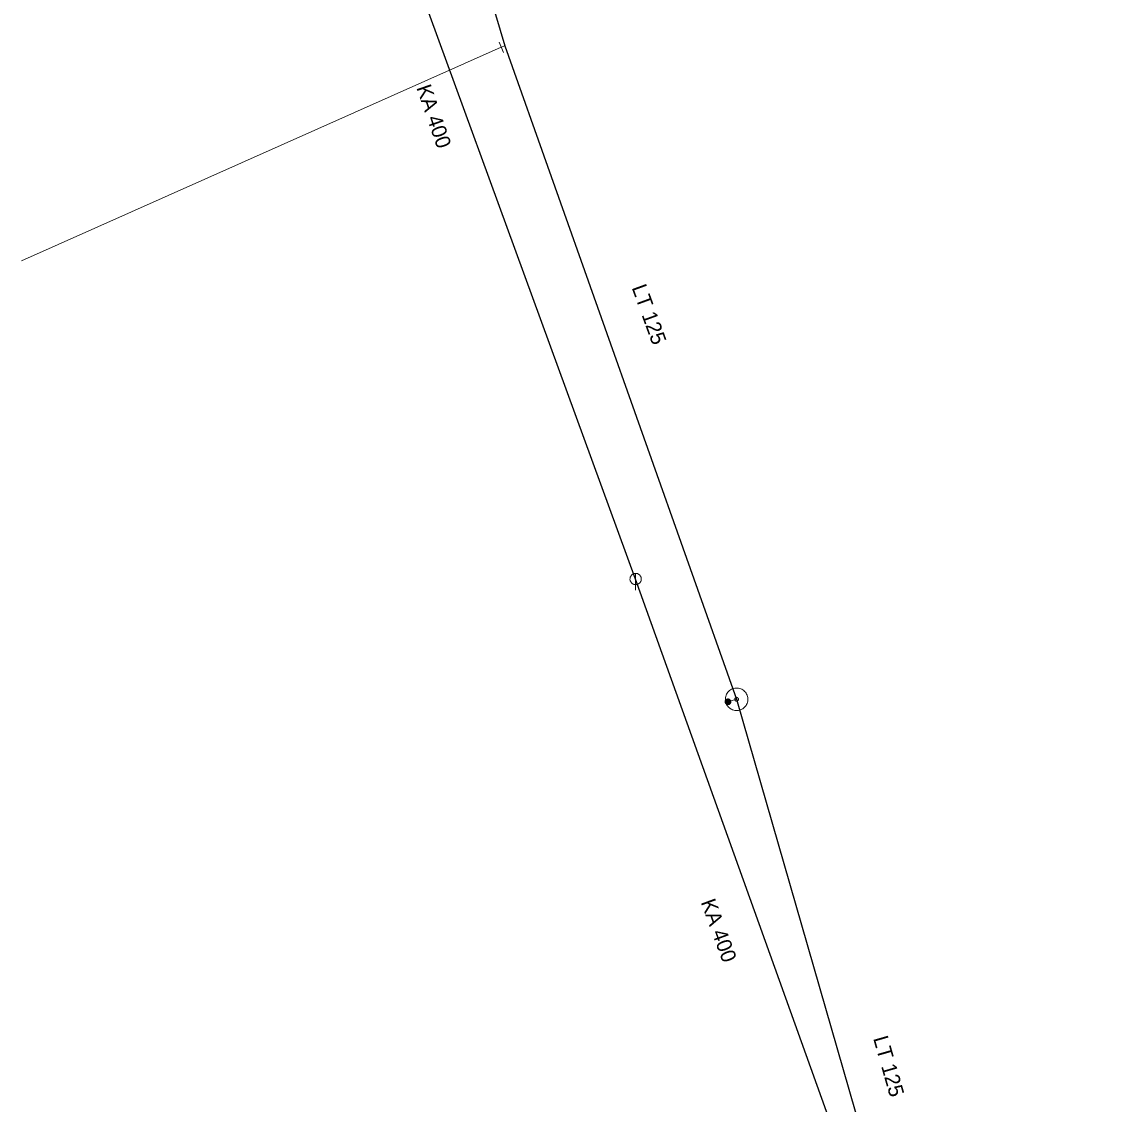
# Model space of a CAD drawing. Extents: x -687515 to -686506, y -974029 to -973461.
# Drawn here: x -687150.06 to -687101.95, y -973553.01 to -973504.79 of the extents above; entities that cross this region are included whole.
import ezdxf
from ezdxf.enums import TextEntityAlignment as Align

# ---------------------------------------------------------------- set-up
doc = ezdxf.new("R2010")
doc.units = 0
doc.header["$LTSCALE"] = 0.27
for name, color, linetype, lineweight in [('1', 7, 'Continuous', 13), ('13', 7, 'Continuous', 13), ('14', 7, 'Continuous', 25), ('17', 7, 'Continuous', 25), ('22', 7, 'Continuous', 13), ('34', 7, 'Continuous', 13), ('47', 7, 'Continuous', 13), ('9', 7, 'Continuous', 13)]:
    doc.layers.add(name, color=color, linetype=linetype, lineweight=lineweight)

msp = doc.modelspace()

# ---------------------------------------------------------------- linework, layer by layer
at = {"layer": '13'}
msp.add_line((-687128.69, -973505.93), (-687150.063, -973515.436), dxfattribs=at)
at = {"layer": '14', "lineweight": 13}
for p, q in [((-687128.537, -973505.866), (-687128.69, -973505.93)), ((-687118.59, -973535.079), (-687118.206, -973534.968))]:
    msp.add_line(p, q, dxfattribs=at)
at = {"layer": '14'}
msp.add_lwpolyline([(-687110.498, -973563.624), (-687122.706, -973529.611), (-687136.829, -973490.92)], dxfattribs=at)
at = {"layer": '17'}
for points in [[(-687132.15, -973493.689), (-687128.537, -973505.866), (-687118.206, -973534.968)], [(-687118.206, -973534.968), (-687107.388, -973572.532), (-687101.954, -973579.133)]]:
    msp.add_lwpolyline(points, dxfattribs=at)
at = {"layer": '22'}
msp.add_line((-687122.705, -973529.359), (-687122.706, -973530.103), dxfattribs=at)
msp.add_lwpolyline([(-687122.454, -973529.611), (-687122.455, -973529.585), (-687122.459, -973529.559), (-687122.465, -973529.533), (-687122.475, -973529.509), (-687122.487, -973529.485), (-687122.501, -973529.463), (-687122.518, -973529.442), (-687122.536, -973529.424), (-687122.557, -973529.407), (-687122.579, -973529.393), (-687122.603, -973529.381), (-687122.627, -973529.371), (-687122.653, -973529.365), (-687122.679, -973529.361), (-687122.705, -973529.359), (-687122.731, -973529.36), (-687122.757, -973529.364), (-687122.783, -973529.37), (-687122.808, -973529.38), (-687122.831, -973529.392), (-687122.853, -973529.406), (-687122.874, -973529.423), (-687122.892, -973529.441), (-687122.909, -973529.462), (-687122.923, -973529.484), (-687122.935, -973529.508), (-687122.945, -973529.532), (-687122.952, -973529.558), (-687122.956, -973529.584), (-687122.958, -973529.61), (-687122.957, -973529.636), (-687122.953, -973529.662), (-687122.946, -973529.688), (-687122.936, -973529.713), (-687122.924, -973529.736), (-687122.91, -973529.758), (-687122.893, -973529.779), (-687122.875, -973529.797), (-687122.854, -973529.814), (-687122.832, -973529.828), (-687122.809, -973529.84), (-687122.784, -973529.85), (-687122.758, -973529.857), (-687122.732, -973529.861), (-687122.706, -973529.863), (-687122.68, -973529.862), (-687122.654, -973529.858), (-687122.628, -973529.851), (-687122.604, -973529.841), (-687122.58, -973529.829), (-687122.558, -973529.815), (-687122.537, -973529.798), (-687122.519, -973529.78), (-687122.502, -973529.759), (-687122.488, -973529.737), (-687122.476, -973529.714), (-687122.466, -973529.689), (-687122.46, -973529.663), (-687122.456, -973529.637)], close=True, dxfattribs=at)
at = {"layer": '34'}
msp.add_line((-687128.79, -973505.703), (-687128.589, -973506.156), dxfattribs=at)
at = {"layer": '47'}
for points in [[(-687118.028, -973535.435), (-687117.98, -973535.414), (-687117.935, -973535.388), (-687117.893, -973535.357), (-687117.854, -973535.323), (-687117.818, -973535.284), (-687117.787, -973535.241), (-687117.762, -973535.196), (-687117.74, -973535.148), (-687117.723, -973535.099), (-687117.712, -973535.048), (-687117.706, -973534.995), (-687117.707, -973534.943), (-687117.711, -973534.891), (-687117.722, -973534.84), (-687117.738, -973534.79), (-687117.759, -973534.742), (-687117.785, -973534.697), (-687117.816, -973534.654), (-687117.85, -973534.616), (-687117.889, -973534.58), (-687117.932, -973534.549), (-687117.978, -973534.523), (-687118.025, -973534.501), (-687118.074, -973534.485), (-687118.125, -973534.474), (-687118.178, -973534.468), (-687118.23, -973534.468), (-687118.282, -973534.473), (-687118.333, -973534.484), (-687118.383, -973534.5), (-687118.431, -973534.521), (-687118.476, -973534.547), (-687118.519, -973534.577), (-687118.557, -973534.612), (-687118.593, -973534.651), (-687118.624, -973534.693), (-687118.651, -973534.739), (-687118.672, -973534.786), (-687118.688, -973534.836), (-687118.699, -973534.887), (-687118.705, -973534.94), (-687118.706, -973534.992), (-687118.7, -973535.044), (-687118.689, -973535.095), (-687118.673, -973535.145), (-687118.652, -973535.193), (-687118.626, -973535.238), (-687118.596, -973535.28), (-687118.561, -973535.319), (-687118.522, -973535.355), (-687118.48, -973535.386), (-687118.435, -973535.412), (-687118.387, -973535.433), (-687118.337, -973535.45), (-687118.286, -973535.461), (-687118.233, -973535.467), (-687118.182, -973535.467), (-687118.129, -973535.462), (-687118.078, -973535.451)], [(-687118.176, -973535.044), (-687118.168, -973535.041), (-687118.161, -973535.036), (-687118.154, -973535.032), (-687118.148, -973535.026), (-687118.142, -973535.019), (-687118.137, -973535.012), (-687118.132, -973535.005), (-687118.129, -973534.997), (-687118.127, -973534.989), (-687118.125, -973534.981), (-687118.124, -973534.972), (-687118.124, -973534.963), (-687118.125, -973534.955), (-687118.126, -973534.947), (-687118.129, -973534.938), (-687118.132, -973534.93), (-687118.137, -973534.923), (-687118.141, -973534.916), (-687118.147, -973534.91), (-687118.154, -973534.904), (-687118.161, -973534.899), (-687118.168, -973534.894), (-687118.176, -973534.891), (-687118.184, -973534.888), (-687118.192, -973534.887), (-687118.201, -973534.886), (-687118.21, -973534.886), (-687118.218, -973534.887), (-687118.226, -973534.888), (-687118.235, -973534.891), (-687118.243, -973534.894), (-687118.25, -973534.899), (-687118.257, -973534.903), (-687118.263, -973534.909), (-687118.269, -973534.916), (-687118.274, -973534.922), (-687118.279, -973534.93), (-687118.282, -973534.938), (-687118.285, -973534.946), (-687118.286, -973534.954), (-687118.287, -973534.963), (-687118.287, -973534.972), (-687118.286, -973534.98), (-687118.285, -973534.988), (-687118.282, -973534.997), (-687118.279, -973535.005), (-687118.274, -973535.012), (-687118.27, -973535.019), (-687118.264, -973535.025), (-687118.257, -973535.031), (-687118.251, -973535.036), (-687118.243, -973535.041), (-687118.235, -973535.044), (-687118.227, -973535.046), (-687118.219, -973535.048), (-687118.21, -973535.049), (-687118.201, -973535.049), (-687118.193, -973535.048), (-687118.185, -973535.047)]]:
    msp.add_lwpolyline(points, close=True, dxfattribs=at)
at = {"layer": '9'}
for points in [[(-687118.463, -973535.079), (-687118.465, -973535.066), (-687118.467, -973535.053), (-687118.47, -973535.04), (-687118.475, -973535.028), (-687118.48, -973535.016), (-687118.488, -973535.005), (-687118.495, -973534.995), (-687118.505, -973534.985), (-687118.516, -973534.977), (-687118.527, -973534.97), (-687118.539, -973534.964), (-687118.551, -973534.959), (-687118.564, -973534.956), (-687118.576, -973534.954), (-687118.59, -973534.953), (-687118.603, -973534.954), (-687118.615, -973534.956), (-687118.629, -973534.959), (-687118.641, -973534.964), (-687118.652, -973534.97), (-687118.664, -973534.977), (-687118.674, -973534.985), (-687118.684, -973534.995), (-687118.691, -973535.005), (-687118.699, -973535.016), (-687118.705, -973535.028), (-687118.71, -973535.04), (-687118.713, -973535.053), (-687118.715, -973535.066), (-687118.716, -973535.079), (-687118.715, -973535.092), (-687118.713, -973535.105), (-687118.71, -973535.118), (-687118.705, -973535.13), (-687118.699, -973535.142), (-687118.691, -973535.153), (-687118.684, -973535.163), (-687118.674, -973535.173), (-687118.664, -973535.181), (-687118.652, -973535.188), (-687118.641, -973535.194), (-687118.629, -973535.199), (-687118.615, -973535.202), (-687118.603, -973535.204), (-687118.59, -973535.205), (-687118.576, -973535.204), (-687118.564, -973535.202), (-687118.551, -973535.199), (-687118.539, -973535.194), (-687118.527, -973535.188), (-687118.516, -973535.181), (-687118.505, -973535.173), (-687118.495, -973535.163), (-687118.488, -973535.153), (-687118.48, -973535.142), (-687118.475, -973535.13), (-687118.47, -973535.118), (-687118.467, -973535.105), (-687118.465, -973535.092)], [(-687118.483, -973535.079), (-687118.483, -973535.068), (-687118.485, -973535.057), (-687118.489, -973535.046), (-687118.493, -973535.036), (-687118.498, -973535.026), (-687118.504, -973535.017), (-687118.511, -973535.008), (-687118.519, -973535), (-687118.527, -973534.993), (-687118.537, -973534.987), (-687118.547, -973534.982), (-687118.556, -973534.978), (-687118.568, -973534.975), (-687118.578, -973534.973), (-687118.59, -973534.973), (-687118.601, -973534.973), (-687118.612, -973534.975), (-687118.623, -973534.978), (-687118.632, -973534.982), (-687118.642, -973534.987), (-687118.652, -973534.993), (-687118.661, -973535), (-687118.669, -973535.008), (-687118.676, -973535.017), (-687118.681, -973535.026), (-687118.686, -973535.036), (-687118.691, -973535.046), (-687118.694, -973535.057), (-687118.696, -973535.068), (-687118.696, -973535.079), (-687118.696, -973535.09), (-687118.694, -973535.101), (-687118.691, -973535.112), (-687118.686, -973535.122), (-687118.681, -973535.132), (-687118.676, -973535.141), (-687118.669, -973535.15), (-687118.661, -973535.158), (-687118.652, -973535.165), (-687118.642, -973535.171), (-687118.632, -973535.176), (-687118.623, -973535.18), (-687118.612, -973535.183), (-687118.601, -973535.185), (-687118.59, -973535.185), (-687118.578, -973535.185), (-687118.568, -973535.183), (-687118.556, -973535.18), (-687118.547, -973535.176), (-687118.537, -973535.171), (-687118.527, -973535.165), (-687118.519, -973535.158), (-687118.511, -973535.15), (-687118.504, -973535.141), (-687118.498, -973535.132), (-687118.493, -973535.122), (-687118.489, -973535.112), (-687118.485, -973535.101), (-687118.483, -973535.09)], [(-687118.502, -973535.079), (-687118.504, -973535.07), (-687118.505, -973535.061), (-687118.507, -973535.052), (-687118.511, -973535.044), (-687118.515, -973535.036), (-687118.52, -973535.028), (-687118.526, -973535.021), (-687118.532, -973535.015), (-687118.539, -973535.009), (-687118.547, -973535.004), (-687118.554, -973535), (-687118.563, -973534.997), (-687118.571, -973534.994), (-687118.581, -973534.993), (-687118.59, -973534.992), (-687118.598, -973534.993), (-687118.608, -973534.994), (-687118.617, -973534.997), (-687118.625, -973535), (-687118.632, -973535.004), (-687118.641, -973535.009), (-687118.647, -973535.015), (-687118.654, -973535.021), (-687118.659, -973535.028), (-687118.664, -973535.036), (-687118.669, -973535.044), (-687118.672, -973535.052), (-687118.674, -973535.061), (-687118.676, -973535.07), (-687118.677, -973535.079), (-687118.676, -973535.088), (-687118.674, -973535.097), (-687118.672, -973535.106), (-687118.669, -973535.114), (-687118.664, -973535.122), (-687118.659, -973535.13), (-687118.654, -973535.137), (-687118.647, -973535.143), (-687118.641, -973535.149), (-687118.632, -973535.154), (-687118.625, -973535.158), (-687118.617, -973535.161), (-687118.608, -973535.164), (-687118.598, -973535.165), (-687118.59, -973535.166), (-687118.581, -973535.165), (-687118.571, -973535.164), (-687118.563, -973535.161), (-687118.554, -973535.158), (-687118.547, -973535.154), (-687118.539, -973535.149), (-687118.532, -973535.143), (-687118.526, -973535.137), (-687118.52, -973535.13), (-687118.515, -973535.122), (-687118.511, -973535.114), (-687118.507, -973535.106), (-687118.505, -973535.097), (-687118.504, -973535.088)], [(-687118.522, -973535.079), (-687118.522, -973535.072), (-687118.525, -973535.065), (-687118.526, -973535.058), (-687118.529, -973535.052), (-687118.532, -973535.046), (-687118.536, -973535.04), (-687118.539, -973535.034), (-687118.544, -973535.029), (-687118.551, -973535.025), (-687118.556, -973535.021), (-687118.563, -973535.018), (-687118.569, -973535.015), (-687118.576, -973535.014), (-687118.583, -973535.012), (-687118.59, -973535.012), (-687118.597, -973535.012), (-687118.603, -973535.014), (-687118.61, -973535.015), (-687118.617, -973535.018), (-687118.624, -973535.021), (-687118.629, -973535.025), (-687118.635, -973535.029), (-687118.64, -973535.034), (-687118.644, -973535.04), (-687118.647, -973535.046), (-687118.651, -973535.052), (-687118.654, -973535.058), (-687118.656, -973535.065), (-687118.657, -973535.072), (-687118.657, -973535.079), (-687118.657, -973535.086), (-687118.656, -973535.093), (-687118.654, -973535.1), (-687118.651, -973535.106), (-687118.647, -973535.113), (-687118.644, -973535.118), (-687118.64, -973535.124), (-687118.635, -973535.129), (-687118.629, -973535.133), (-687118.624, -973535.137), (-687118.617, -973535.14), (-687118.61, -973535.143), (-687118.603, -973535.145), (-687118.597, -973535.146), (-687118.59, -973535.146), (-687118.583, -973535.146), (-687118.576, -973535.145), (-687118.569, -973535.143), (-687118.563, -973535.14), (-687118.556, -973535.137), (-687118.551, -973535.133), (-687118.544, -973535.129), (-687118.539, -973535.124), (-687118.536, -973535.118), (-687118.532, -973535.113), (-687118.529, -973535.106), (-687118.526, -973535.1), (-687118.525, -973535.093), (-687118.522, -973535.086)], [(-687118.543, -973535.079), (-687118.543, -973535.074), (-687118.544, -973535.069), (-687118.544, -973535.064), (-687118.547, -973535.06), (-687118.549, -973535.055), (-687118.552, -973535.051), (-687118.554, -973535.048), (-687118.559, -973535.044), (-687118.561, -973535.041), (-687118.566, -973535.038), (-687118.571, -973535.036), (-687118.575, -973535.034), (-687118.58, -973535.033), (-687118.585, -973535.032), (-687118.59, -973535.032), (-687118.595, -973535.032), (-687118.6, -973535.033), (-687118.605, -973535.034), (-687118.608, -973535.036), (-687118.614, -973535.038), (-687118.618, -973535.041), (-687118.622, -973535.044), (-687118.625, -973535.048), (-687118.627, -973535.051), (-687118.63, -973535.055), (-687118.632, -973535.06), (-687118.635, -973535.064), (-687118.636, -973535.069), (-687118.637, -973535.074), (-687118.637, -973535.079), (-687118.637, -973535.084), (-687118.636, -973535.089), (-687118.635, -973535.094), (-687118.632, -973535.098), (-687118.63, -973535.103), (-687118.627, -973535.107), (-687118.625, -973535.111), (-687118.622, -973535.114), (-687118.618, -973535.117), (-687118.614, -973535.12), (-687118.608, -973535.122), (-687118.605, -973535.124), (-687118.6, -973535.125), (-687118.595, -973535.126), (-687118.59, -973535.126), (-687118.585, -973535.126), (-687118.58, -973535.125), (-687118.575, -973535.124), (-687118.571, -973535.122), (-687118.566, -973535.12), (-687118.561, -973535.117), (-687118.559, -973535.114), (-687118.554, -973535.111), (-687118.552, -973535.107), (-687118.549, -973535.103), (-687118.547, -973535.098), (-687118.544, -973535.094), (-687118.544, -973535.089), (-687118.543, -973535.084)], [(-687118.563, -973535.079), (-687118.563, -973535.076), (-687118.563, -973535.073), (-687118.564, -973535.071), (-687118.565, -973535.068), (-687118.566, -973535.065), (-687118.568, -973535.063), (-687118.57, -973535.061), (-687118.571, -973535.059), (-687118.574, -973535.057), (-687118.576, -973535.055), (-687118.578, -973535.054), (-687118.581, -973535.053), (-687118.583, -973535.052), (-687118.587, -973535.052), (-687118.59, -973535.052), (-687118.593, -973535.052), (-687118.596, -973535.052), (-687118.598, -973535.053), (-687118.601, -973535.054), (-687118.603, -973535.055), (-687118.605, -973535.057), (-687118.608, -973535.059), (-687118.61, -973535.061), (-687118.612, -973535.063), (-687118.614, -973535.065), (-687118.615, -973535.068), (-687118.615, -973535.071), (-687118.617, -973535.073), (-687118.617, -973535.076), (-687118.618, -973535.079), (-687118.617, -973535.082), (-687118.617, -973535.085), (-687118.615, -973535.088), (-687118.615, -973535.09), (-687118.614, -973535.093), (-687118.612, -973535.095), (-687118.61, -973535.098), (-687118.608, -973535.1), (-687118.605, -973535.101), (-687118.603, -973535.103), (-687118.601, -973535.104), (-687118.598, -973535.105), (-687118.596, -973535.106), (-687118.593, -973535.106), (-687118.59, -973535.107), (-687118.587, -973535.106), (-687118.583, -973535.106), (-687118.581, -973535.105), (-687118.578, -973535.104), (-687118.576, -973535.103), (-687118.574, -973535.101), (-687118.571, -973535.1), (-687118.57, -973535.098), (-687118.568, -973535.095), (-687118.566, -973535.093), (-687118.565, -973535.09), (-687118.564, -973535.088), (-687118.563, -973535.085), (-687118.563, -973535.082)], [(-687118.581, -973535.079), (-687118.581, -973535.078), (-687118.581, -973535.077), (-687118.583, -973535.077), (-687118.583, -973535.076), (-687118.583, -973535.075), (-687118.583, -973535.074), (-687118.583, -973535.074), (-687118.585, -973535.073), (-687118.585, -973535.073), (-687118.586, -973535.072), (-687118.587, -973535.072), (-687118.588, -973535.072), (-687118.588, -973535.071), (-687118.588, -973535.071), (-687118.59, -973535.071), (-687118.591, -973535.071), (-687118.592, -973535.071), (-687118.592, -973535.072), (-687118.593, -973535.072), (-687118.593, -973535.072), (-687118.595, -973535.073), (-687118.595, -973535.073), (-687118.596, -973535.074), (-687118.596, -973535.074), (-687118.597, -973535.075), (-687118.597, -973535.076), (-687118.598, -973535.077), (-687118.598, -973535.077), (-687118.598, -973535.078), (-687118.598, -973535.079), (-687118.598, -973535.08), (-687118.598, -973535.081), (-687118.598, -973535.081), (-687118.597, -973535.082), (-687118.597, -973535.083), (-687118.596, -973535.084), (-687118.596, -973535.084), (-687118.595, -973535.085), (-687118.595, -973535.085), (-687118.593, -973535.086), (-687118.593, -973535.086), (-687118.592, -973535.087), (-687118.592, -973535.087), (-687118.591, -973535.087), (-687118.59, -973535.087), (-687118.588, -973535.087), (-687118.588, -973535.087), (-687118.588, -973535.087), (-687118.587, -973535.086), (-687118.586, -973535.086), (-687118.585, -973535.085), (-687118.585, -973535.085), (-687118.583, -973535.084), (-687118.583, -973535.084), (-687118.583, -973535.083), (-687118.583, -973535.082), (-687118.583, -973535.081), (-687118.581, -973535.081), (-687118.581, -973535.08)]]:
    msp.add_lwpolyline(points, close=True, dxfattribs=at)

# ---------------------------------------------------------------- texts
at = {"layer": '1'}
for s, rotation, p in [('KA 400', 289, (-687132.006, -973509.108)), ('LT 125', 290, (-687122.413, -973517.934)), ('KA 400', 290, (-687119.31, -973545.373)), ('LT 125', 286, (-687111.745, -973551.399))]:
    msp.add_text(s, height=0.6667, rotation=rotation, dxfattribs=at).set_placement(p, align=Align.CENTER)

doc.saveas('drawing.dxf')
